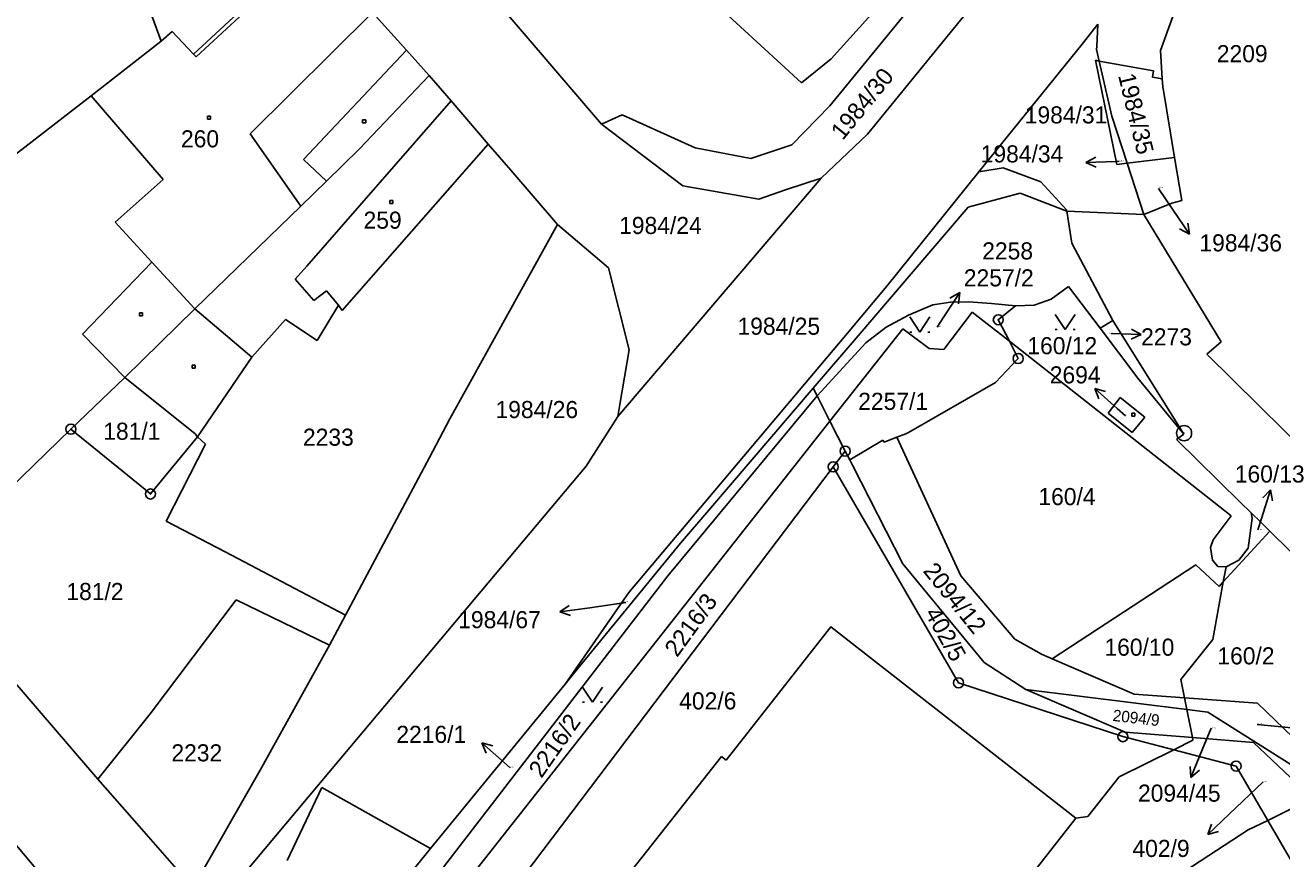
# Model space of a CAD drawing. Extents: x -795483 to -789093, y -1112258 to -1108741.
# Drawn here: x -791614.7 to -791489.6, y -1110839.7 to -1110756.8 of the extents above; entities that cross this region are included whole.
import ezdxf

# ---------------------------------------------------------------- set-up
doc = ezdxf.new("R2010")
doc.units = 0
for name, color, linetype in [('Komunikace', 7, 'Continuous'), ('Vrstva 1', 7, 'Continuous'), ('Vrstva 14', 7, 'Continuous'), ('Vrstva 15', 7, 'Continuous'), ('Vrstva 16', 7, 'Continuous'), ('Vrstva 2', 7, 'Continuous'), ('Vrstva 23', 7, 'Continuous'), ('Vrstva 25', 7, 'Continuous'), ('Vrstva 28', 7, 'Continuous')]:
    doc.layers.add(name, color=color, linetype=linetype)

msp = doc.modelspace()

# ---------------------------------------------------------------- linework, layer by layer
at = {"layer": 'Komunikace'}
for p, q in [((-791505.83, -1110770.29), (-791506.12, -1110770.3)), ((-791501.9, -1110772.99), (-791500.5, -1110775.07)), ((-791523.94, -1110786.79), (-791523.33, -1110785.87)), ((-791506.62, -1110787.43), (-791506.61, -1110787.43)), ((-791505.18, -1110795.61), (-791506.01, -1110794.88)), ((-791492, -1110806.97), (-791491.64, -1110805.83)), ((-791554.89, -1110814.18), (-791558.49, -1110814.7)), ((-791496.67, -1110826.69), (-791497.54, -1110828.83)), ((-791492.08, -1110826.31), (-791489.98, -1110826.52)), ((-791566.41, -1110830.63), (-791566.98, -1110830.13)), ((-791491.5, -1110832.03), (-791494.83, -1110835.21))]:
    msp.add_line(p, q, dxfattribs=at)
at = {"layer": 'Vrstva 1'}
for p, q in [((-791557.32, -1110766.6), (-791576.75, -1110743.88)), ((-791604.15, -1110750.16), (-791601.15, -1110758.36)), ((-791525.05, -1110749.65), (-791534.46, -1110760.12)), ((-791523.41, -1110751.11), (-791534.59, -1110764.78)), ((-791590.39, -1110752.64), (-791597.91, -1110759.63)), ((-791576.73, -1110759.25), (-791580.1, -1110755.51)), ((-791537.41, -1110762.48), (-791545.52, -1110755.06)), ((-791530.87, -1110767.6), (-791520.59, -1110755)), ((-791507.95, -1110756.65), (-791508.05, -1110758.87)), ((-791501.7, -1110759.26), (-791500.47, -1110755.89)), ((-791600.06, -1110757.38), (-791601.15, -1110758.36)), ((-791597.91, -1110759.63), (-791600.06, -1110757.38)), ((-791601.15, -1110758.36), (-791608.09, -1110763.77)), ((-791574.46, -1110761.76), (-791576.73, -1110759.25)), ((-791508.05, -1110758.87), (-791508.06, -1110759.18)), ((-791508.06, -1110759.18), (-791507.8, -1110760.32)), ((-791501.52, -1110762.1), (-791501.7, -1110759.26)), ((-791534.46, -1110760.12), (-791537.41, -1110762.48)), ((-791508.16, -1110760.25), (-791506.03, -1110770.61)), ((-791507.8, -1110760.32), (-791508.16, -1110760.25)), ((-791507.8, -1110760.32), (-791506.56, -1110765.8)), ((-791507.8, -1110760.32), (-791502.39, -1110761.31)), ((-791574.46, -1110761.76), (-791581.41, -1110769.04)), ((-791572.29, -1110764.29), (-791574.46, -1110761.76)), ((-791502.39, -1110761.31), (-791502.5, -1110761.93)), ((-791502.5, -1110761.93), (-791501.52, -1110762.1)), ((-791501.52, -1110762.1), (-791501.47, -1110762.86)), ((-791501.47, -1110762.86), (-791500.3, -1110769.93)), ((-791608.09, -1110763.77), (-791635.81, -1110785.17)), ((-791600.94, -1110772.11), (-791608.09, -1110763.77)), ((-791568.6, -1110768.59), (-791572.29, -1110764.29)), ((-791555.27, -1110765.66), (-791557.32, -1110766.6)), ((-791548.02, -1110768.95), (-791555.27, -1110765.66)), ((-791534.59, -1110764.78), (-791538.38, -1110768.66)), ((-791557.32, -1110766.6), (-791549.24, -1110772.73)), ((-791506.56, -1110765.8), (-791505.03, -1110770.49)), ((-791535.47, -1110771.97), (-791530.87, -1110767.6)), ((-791581.41, -1110769.04), (-791584.7, -1110772.26)), ((-791568.6, -1110768.59), (-791583.14, -1110785.13)), ((-791566.36, -1110771.19), (-791568.6, -1110768.59)), ((-791542.47, -1110770.01), (-791548.02, -1110768.95)), ((-791538.38, -1110768.66), (-791542.47, -1110770.01)), ((-791506.03, -1110770.61), (-791505.03, -1110770.49)), ((-791505.03, -1110770.49), (-791500.3, -1110769.93)), ((-791503.37, -1110775.6), (-791505.03, -1110770.49)), ((-791499.58, -1110774.19), (-791500.3, -1110769.93)), ((-791561.7, -1110776.6), (-791566.36, -1110771.19)), ((-791555.71, -1110795.69), (-791535.47, -1110771.97)), ((-791539, -1110773.15), (-791535.47, -1110771.97)), ((-791528.94, -1110782.71), (-791519.78, -1110771.36)), ((-791519.78, -1110771.36), (-791517.34, -1110770.93)), ((-791517.34, -1110770.93), (-791513.61, -1110772.34)), ((-791605.73, -1110776.36), (-791600.94, -1110772.11)), ((-791584.7, -1110772.26), (-791587.25, -1110774.75)), ((-791549.24, -1110772.73), (-791541.68, -1110774.05)), ((-791541.68, -1110774.05), (-791539, -1110773.15)), ((-791513.61, -1110772.34), (-791511.04, -1110775.12)), ((-791520.85, -1110774.86), (-791515.65, -1110773.46)), ((-791515.65, -1110773.46), (-791511.01, -1110775.27)), ((-791503.37, -1110775.6), (-791500.58, -1110774.47)), ((-791500.58, -1110774.47), (-791499.58, -1110774.19)), ((-791587.25, -1110774.75), (-791597.78, -1110784.98)), ((-791532, -1110787.88), (-791520.85, -1110774.86)), ((-791511.04, -1110775.12), (-791511.01, -1110775.27)), ((-791511.01, -1110775.27), (-791503.37, -1110775.6)), ((-791510.54, -1110778.44), (-791511.01, -1110775.27)), ((-791503.37, -1110775.6), (-791495.65, -1110788.26)), ((-791602.06, -1110780.34), (-791605.73, -1110776.36)), ((-791569.03, -1110789.83), (-791561.7, -1110776.6)), ((-791561.7, -1110776.6), (-791556.63, -1110780.89)), ((-791510.54, -1110778.44), (-791506.46, -1110786.14)), ((-791608.98, -1110787.48), (-791602.06, -1110780.34)), ((-791556.63, -1110780.89), (-791554.58, -1110789.04)), ((-791512.57, -1110784), (-791510.84, -1110782.74)), ((-791510.84, -1110782.74), (-791507.71, -1110786.9)), ((-791524.34, -1110784.59), (-791522.61, -1110784.3)), ((-791522.61, -1110784.3), (-791520.8, -1110784.26)), ((-791520.8, -1110784.26), (-791518.52, -1110784.44)), ((-791518.52, -1110784.44), (-791516.12, -1110784.69)), ((-791514.26, -1110784.6), (-791512.57, -1110784)), ((-791597.78, -1110784.98), (-791604.77, -1110791.79)), ((-791583.49, -1110784.62), (-791585.62, -1110788.13)), ((-791583.14, -1110785.13), (-791583.49, -1110784.62)), ((-791528.99, -1110786.8), (-791526.76, -1110785.59)), ((-791526.76, -1110785.59), (-791524.34, -1110784.59)), ((-791523.27, -1110789.02), (-791520.43, -1110785.3)), ((-791520.43, -1110785.3), (-791516.74, -1110788.2)), ((-791517.84, -1110786.06), (-791516.12, -1110784.69)), ((-791516.12, -1110784.69), (-791514.26, -1110784.6)), ((-791588.76, -1110786.04), (-791592.11, -1110789.77)), ((-791585.62, -1110788.13), (-791588.76, -1110786.04)), ((-791534.59, -1110796.15), (-791527.34, -1110786.97)), ((-791531.01, -1110788.36), (-791528.99, -1110786.8)), ((-791527.34, -1110786.97), (-791524.71, -1110788.93)), ((-791517.46, -1110786.8), (-791517.84, -1110786.06)), ((-791517.46, -1110786.8), (-791516.74, -1110788.2)), ((-791507.71, -1110786.9), (-791506.46, -1110786.14)), ((-791507.71, -1110786.9), (-791503.97, -1110791.88)), ((-791506.46, -1110786.14), (-791499.38, -1110797.43)), ((-791604.77, -1110791.79), (-791608.98, -1110787.48)), ((-791536.27, -1110792.87), (-791532, -1110787.88)), ((-791516.74, -1110788.2), (-791494.66, -1110805.56)), ((-791516.74, -1110788.2), (-791515.86, -1110789.91)), ((-791495.65, -1110788.26), (-791497.1, -1110789.47)), ((-791554.58, -1110789.04), (-791555.51, -1110794.5)), ((-791535.88, -1110793.62), (-791531.01, -1110788.36)), ((-791524.71, -1110788.93), (-791523.27, -1110789.02)), ((-791497.1, -1110789.47), (-791478.33, -1110808.03)), ((-791592.11, -1110789.77), (-791597.51, -1110797.69)), ((-791572.41, -1110795.93), (-791569.03, -1110789.83)), ((-791515.86, -1110789.91), (-791518.11, -1110792.3)), ((-791604.77, -1110791.79), (-791610.12, -1110796.94)), ((-791597.77, -1110797.41), (-791604.77, -1110791.79)), ((-791503.97, -1110791.88), (-791499.38, -1110797.43)), ((-791536.27, -1110792.87), (-791546.66, -1110805)), ((-791536.27, -1110792.87), (-791535.88, -1110793.62)), ((-791518.11, -1110792.3), (-791526.78, -1110797.26)), ((-791555.51, -1110794.5), (-791555.71, -1110795.69)), ((-791550.73, -1110811.52), (-791535.88, -1110793.62)), ((-791535.88, -1110793.62), (-791534.59, -1110796.15)), ((-791506.91, -1110795.34), (-791505.7, -1110793.79)), ((-791505.7, -1110793.79), (-791503.27, -1110795.76)), ((-791558.84, -1110800.63), (-791555.71, -1110795.69)), ((-791504.52, -1110797.29), (-791506.91, -1110795.34)), ((-791503.27, -1110795.76), (-791504.52, -1110797.29)), ((-791610.12, -1110796.94), (-791624.88, -1110811.16)), ((-791610.12, -1110796.94), (-791602.21, -1110803.39)), ((-791578.3, -1110851.53), (-791534.59, -1110796.15)), ((-791574.45, -1110799.76), (-791572.41, -1110795.93)), ((-791534.59, -1110796.15), (-791533.08, -1110799.12)), ((-791602.21, -1110803.39), (-791597.51, -1110797.69)), ((-791597.51, -1110797.69), (-791597.77, -1110797.41)), ((-791596.72, -1110798.42), (-791597.51, -1110797.69)), ((-791529.33, -1110798.03), (-791532.63, -1110800)), ((-791529.2, -1110798.23), (-791529.33, -1110798.03)), ((-791527.95, -1110797.73), (-791529.2, -1110798.23)), ((-791527.04, -1110797.41), (-791527.95, -1110797.73)), ((-791527.95, -1110797.73), (-791521.58, -1110811.54)), ((-791526.78, -1110797.26), (-791527.04, -1110797.41)), ((-791499.38, -1110797.43), (-791500.12, -1110797.97)), ((-791500.12, -1110797.97), (-791493.77, -1110804.2)), ((-791600.65, -1110806.08), (-791596.72, -1110798.42)), ((-791534.26, -1110800.69), (-791533.08, -1110799.12)), ((-791533.08, -1110799.12), (-791532.63, -1110800)), ((-791584.45, -1110831.1), (-791558.84, -1110800.63)), ((-791582.79, -1110815.43), (-791574.45, -1110799.76)), ((-791574.8, -1110854.23), (-791534.26, -1110800.69)), ((-791534.26, -1110800.69), (-791521.79, -1110822.18)), ((-791532.63, -1110800), (-791532.35, -1110800.53)), ((-791532.35, -1110800.53), (-791527.33, -1110810.34)), ((-791605.22, -1110850.5), (-791647.25, -1110801.07)), ((-791492.67, -1110805.28), (-791493.77, -1110804.2)), ((-791546.66, -1110805), (-791549.47, -1110808.29)), ((-791494.66, -1110805.56), (-791496.47, -1110807.95)), ((-791492.99, -1110808.79), (-791492.58, -1110805.78)), ((-791492.58, -1110805.78), (-791492.67, -1110805.28)), ((-791491.73, -1110806.2), (-791492.67, -1110805.28)), ((-791594.78, -1110809.15), (-791600.65, -1110806.08)), ((-791491.73, -1110806.2), (-791490.83, -1110807.08)), ((-791496.47, -1110807.95), (-791496.72, -1110808.7)), ((-791490.83, -1110807.08), (-791495.46, -1110812.14)), ((-791486.83, -1110811), (-791490.83, -1110807.08)), ((-791582.79, -1110815.43), (-791594.78, -1110809.15)), ((-791560.28, -1110821.49), (-791549.47, -1110808.29)), ((-791496.72, -1110808.7), (-791496.52, -1110809.97)), ((-791493.9, -1110809.99), (-791492.99, -1110808.79)), ((-791519.25, -1110820.14), (-791527.33, -1110810.34)), ((-791498.2, -1110810.44), (-791512.48, -1110819.79)), ((-791498.2, -1110810.44), (-791495.88, -1110812.6)), ((-791496.52, -1110809.97), (-791495.98, -1110810.59)), ((-791495.98, -1110810.59), (-791495.18, -1110810.64)), ((-791495.18, -1110810.64), (-791495.46, -1110812.14)), ((-791495.18, -1110810.64), (-791493.9, -1110809.99)), ((-791580.34, -1110849.96), (-791550.73, -1110811.52)), ((-791521.58, -1110811.54), (-791516.18, -1110817.82)), ((-791560.95, -1110822.31), (-791554.62, -1110813.19)), ((-791495.46, -1110812.14), (-791496.51, -1110817.85)), ((-791495.46, -1110812.14), (-791495.88, -1110812.6)), ((-791593.67, -1110813.93), (-791602.25, -1110825.26)), ((-791584.39, -1110818.43), (-791593.67, -1110813.93)), ((-791584.39, -1110818.43), (-791582.79, -1110815.43)), ((-791516.18, -1110817.82), (-791513.53, -1110819.34)), ((-791496.51, -1110817.85), (-791499.68, -1110821.85)), ((-791607.45, -1110831.76), (-791618.71, -1110818.65)), ((-791591.29, -1110830.86), (-791584.39, -1110818.43)), ((-791513.53, -1110819.34), (-791512.48, -1110819.79)), ((-791510.13, -1110835.65), (-791530.55, -1110819.68)), ((-791515.09, -1110822.85), (-791519.25, -1110820.14)), ((-791512.48, -1110819.79), (-791504.32, -1110823.3)), ((-791560.95, -1110822.31), (-791560.28, -1110821.49)), ((-791499.68, -1110821.85), (-791499.32, -1110823.66)), ((-791574.34, -1110838.66), (-791560.95, -1110822.31)), ((-791521.79, -1110822.18), (-791505.44, -1110827.53)), ((-791515.09, -1110822.85), (-791505.22, -1110827.08)), ((-791499.08, -1110824.84), (-791515.09, -1110822.85)), ((-791504.32, -1110823.3), (-791499.32, -1110823.66)), ((-791499.32, -1110823.66), (-791499.08, -1110824.84)), ((-791499.32, -1110823.66), (-791498.4, -1110823.73)), ((-791498.4, -1110823.73), (-791492.04, -1110824.2)), ((-791492.04, -1110824.2), (-791483.14, -1110832.78)), ((-791602.25, -1110825.26), (-791607.45, -1110831.76)), ((-791499.08, -1110824.84), (-791498.52, -1110827.63)), ((-791496.99, -1110825.1), (-791499.08, -1110824.84)), ((-791488.09, -1110830.7), (-791496.99, -1110825.1)), ((-791505.44, -1110827.53), (-791500.39, -1110828.84)), ((-791498.52, -1110827.63), (-791505.22, -1110827.08)), ((-791498.47, -1110827.89), (-791500.39, -1110828.84)), ((-791498.52, -1110827.63), (-791498.47, -1110827.89)), ((-791492.46, -1110828.12), (-791498.52, -1110827.63)), ((-791492.46, -1110828.12), (-791486.94, -1110833.33)), ((-791558.89, -1110846.63), (-791545.39, -1110829.5)), ((-791545.39, -1110829.5), (-791544.92, -1110829.88)), ((-791500.39, -1110828.84), (-791505.82, -1110831.54)), ((-791500.39, -1110828.84), (-791494.18, -1110830.46)), ((-791491.03, -1110835.86), (-791494.18, -1110830.46)), ((-791603.32, -1110836.45), (-791607.45, -1110831.76)), ((-791601.94, -1110851.92), (-791584.45, -1110831.1)), ((-791597.97, -1110842.53), (-791591.29, -1110830.86)), ((-791505.82, -1110831.54), (-791508.92, -1110835.48)), ((-791585.15, -1110832.59), (-791588.59, -1110839.85)), ((-791585.15, -1110832.59), (-791574.34, -1110838.66)), ((-791487.29, -1110834.03), (-791491.03, -1110835.86)), ((-791508.92, -1110835.48), (-791510.13, -1110835.65)), ((-791597.97, -1110842.53), (-791603.32, -1110836.45)), ((-791492.97, -1110836.81), (-791499.29, -1110840.92)), ((-791491.03, -1110835.86), (-791492.97, -1110836.81)), ((-791486.66, -1110843.36), (-791491.03, -1110835.86)), ((-791574.34, -1110838.66), (-791582.34, -1110848.43))]:
    msp.add_line(p, q, dxfattribs=at)
for points in [[(-791519.78, -1110771.36), (-791509.5, -1110758.63), (-791507.95, -1110756.65)], [(-791554.62, -1110813.19), (-791532.84, -1110787.38), (-791528.94, -1110782.71)], [(-791530.55, -1110819.68), (-791534.49, -1110816.59), (-791544.92, -1110829.88)], [(-791523.23, -1110862.08), (-791520.01, -1110857.95), (-791524.72, -1110854.28), (-791510.13, -1110835.65)]]:
    msp.add_lwpolyline(points, dxfattribs=at)
at = {"layer": 'Vrstva 16'}
for p, q in [((-791509.12, -1110770.41), (-791508.14, -1110769.87)), ((-791506.12, -1110770.3), (-791509.12, -1110770.41)), ((-791509.12, -1110770.41), (-791508.1, -1110770.87)), ((-791500.5, -1110775.07), (-791498.83, -1110777.56)), ((-791498.83, -1110777.56), (-791499.8, -1110777.01)), ((-791498.83, -1110777.56), (-791498.97, -1110776.45)), ((-791523.33, -1110785.87), (-791521.68, -1110783.36)), ((-791521.68, -1110783.36), (-791522.65, -1110783.92)), ((-791521.68, -1110783.36), (-791521.81, -1110784.47)), ((-791503.61, -1110787.52), (-791504.59, -1110786.99)), ((-791506.61, -1110787.43), (-791503.61, -1110787.52)), ((-791503.61, -1110787.52), (-791504.63, -1110787.99)), ((-791506.01, -1110794.88), (-791508.25, -1110792.89)), ((-791508.25, -1110792.89), (-791507.84, -1110793.93)), ((-791508.25, -1110792.89), (-791507.17, -1110793.18)), ((-791491.64, -1110805.83), (-791490.74, -1110802.97)), ((-791490.74, -1110802.97), (-791491.52, -1110803.77)), ((-791490.74, -1110802.97), (-791490.57, -1110804.07)), ((-791561.46, -1110815.13), (-791560.54, -1110814.49)), ((-791558.49, -1110814.7), (-791561.46, -1110815.13)), ((-791561.46, -1110815.13), (-791560.4, -1110815.48)), ((-791489.98, -1110826.52), (-791486.99, -1110826.81)), ((-791566.98, -1110830.13), (-791569.23, -1110828.15)), ((-791569.23, -1110828.15), (-791568.81, -1110829.18)), ((-791569.23, -1110828.15), (-791568.15, -1110828.43)), ((-791497.54, -1110828.83), (-791498.67, -1110831.61)), ((-791498.67, -1110831.61), (-791498.76, -1110830.49)), ((-791498.67, -1110831.61), (-791497.83, -1110830.87)), ((-791494.83, -1110835.21), (-791497, -1110837.28)), ((-791497, -1110837.28), (-791496.62, -1110836.23)), ((-791497, -1110837.28), (-791495.93, -1110836.95))]:
    msp.add_line(p, q, dxfattribs=at)
at = {"layer": 'Vrstva 2'}
for p, q in [((-791585.95, -1110749.02), (-791597.64, -1110759.92)), ((-791592.28, -1110767.57), (-791580.1, -1110755.51)), ((-791586.97, -1110770.13), (-791576.73, -1110759.25)), ((-791597.91, -1110759.63), (-791597.64, -1110759.92)), ((-791572.29, -1110764.29), (-791586.66, -1110780.72)), ((-791587.25, -1110774.75), (-791592.28, -1110767.57)), ((-791584.7, -1110772.26), (-791586.97, -1110770.13)), ((-791602.06, -1110780.34), (-791597.78, -1110784.98)), ((-791586.66, -1110780.72), (-791587.79, -1110782.02)), ((-791587.79, -1110782.02), (-791585.94, -1110784.16)), ((-791585.94, -1110784.16), (-791584.7, -1110783.17)), ((-791584.7, -1110783.17), (-791583.49, -1110784.62)), ((-791597.78, -1110784.98), (-791592.11, -1110789.77))]:
    msp.add_line(p, q, dxfattribs=at)
at = {"layer": 'Vrstva 23'}
for p, q in [((-791512.18, -1110785.52), (-791511.18, -1110787.02)), ((-791511.18, -1110787.02), (-791510.18, -1110785.52)), ((-791526.65, -1110785.78), (-791525.65, -1110787.28)), ((-791525.65, -1110787.28), (-791524.65, -1110785.78)), ((-791512.18, -1110787.02), (-791511.98, -1110787.02)), ((-791510.38, -1110787.02), (-791510.18, -1110787.02)), ((-791526.65, -1110787.28), (-791526.45, -1110787.28)), ((-791524.85, -1110787.28), (-791524.65, -1110787.28)), ((-791559.21, -1110822.6), (-791558.21, -1110824.1)), ((-791558.21, -1110824.1), (-791557.21, -1110822.6)), ((-791559.21, -1110824.1), (-791559.01, -1110824.1)), ((-791557.41, -1110824.1), (-791557.21, -1110824.1))]:
    msp.add_line(p, q, dxfattribs=at)
at = {"layer": 'Vrstva 25'}
for p, q in [((-791596.53, -1110765.8), (-791596.23, -1110765.8)), ((-791596.53, -1110766.1), (-791596.53, -1110765.8)), ((-791596.23, -1110766.1), (-791596.53, -1110766.1)), ((-791596.23, -1110765.8), (-791596.23, -1110766.1)), ((-791581.09, -1110766.18), (-791580.79, -1110766.18)), ((-791581.09, -1110766.48), (-791581.09, -1110766.18)), ((-791580.79, -1110766.48), (-791581.09, -1110766.48)), ((-791580.79, -1110766.18), (-791580.79, -1110766.48)), ((-791578.4, -1110774.19), (-791578.1, -1110774.19)), ((-791578.4, -1110774.49), (-791578.4, -1110774.19)), ((-791578.1, -1110774.49), (-791578.4, -1110774.49)), ((-791578.1, -1110774.19), (-791578.1, -1110774.49)), ((-791603.29, -1110785.38), (-791602.99, -1110785.38)), ((-791603.29, -1110785.68), (-791603.29, -1110785.38)), ((-791602.99, -1110785.68), (-791603.29, -1110785.68)), ((-791602.99, -1110785.38), (-791602.99, -1110785.68)), ((-791598.04, -1110790.56), (-791597.74, -1110790.56)), ((-791598.04, -1110790.86), (-791598.04, -1110790.56)), ((-791597.74, -1110790.56), (-791597.74, -1110790.86)), ((-791597.74, -1110790.86), (-791598.04, -1110790.86)), ((-791504.55, -1110795.34), (-791504.25, -1110795.34)), ((-791504.55, -1110795.64), (-791504.55, -1110795.34)), ((-791504.25, -1110795.64), (-791504.55, -1110795.64)), ((-791504.25, -1110795.34), (-791504.25, -1110795.64))]:
    msp.add_line(p, q, dxfattribs=at)
at = {"layer": 'Vrstva 28'}
for centre, radius in [((-791517.84, -1110786.06), 0.5), ((-791517.84, -1110786.06), 0.01), ((-791515.86, -1110789.91), 0.5), ((-791515.86, -1110789.91), 0.01), ((-791610.12, -1110796.94), 0.5), ((-791610.12, -1110796.94), 0.01), ((-791499.35, -1110797.34), 0.75), ((-791499.35, -1110797.34), 0.01), ((-791533.08, -1110799.12), 0.5), ((-791533.08, -1110799.12), 0.01), ((-791534.26, -1110800.69), 0.5), ((-791534.26, -1110800.69), 0.01), ((-791602.21, -1110803.39), 0.5), ((-791602.21, -1110803.39), 0.01), ((-791521.79, -1110822.18), 0.5), ((-791521.79, -1110822.18), 0.01), ((-791505.44, -1110827.53), 0.5), ((-791505.44, -1110827.53), 0.01), ((-791494.18, -1110830.46), 0.5), ((-791494.18, -1110830.46), 0.01)]:
    msp.add_circle(centre, radius, dxfattribs=at)

# ---------------------------------------------------------------- texts
at = {"layer": 'Vrstva 14'}
for s, height, p in [('2209', 1.7, (-791496.1, -1110760.44)), ('1984/31', 1.7, (-791515.21, -1110766.53)), ('1984/34', 0.1, (-791505.83, -1110770.29)), ('1984/36', 0.1, (-791501.9, -1110772.99)), ('1984/24', 1.7, (-791555.57, -1110777.53)), ('2258', 1.7, (-791519.44, -1110780.06)), ('1984/25', 1.7, (-791543.79, -1110787.55)), ('2257/2', 0.1, (-791523.94, -1110786.79)), ('160/12', 1.7, (-791514.95, -1110789.49)), ('2273', 0.1, (-791506.8, -1110787.43)), ('2257/1', 1.7, (-791531.78, -1110795.02)), ('1984/26', 1.7, (-791567.87, -1110795.84)), ('181/1', 1.7, (-791606.9, -1110798)), ('2233', 1.7, (-791587.03, -1110798.59)), ('160/4', 1.7, (-791513.85, -1110804.5)), ('160/13', 0.1, (-791492, -1110806.97)), ('181/2', 1.7, (-791610.57, -1110813.94)), ('1984/67', 0.1, (-791555.17, -1110814.18)), ('160/10', 1.7, (-791507.28, -1110819.48)), ('160/2', 1.7, (-791496.04, -1110820.34)), ('402/6', 1.7, (-791549.59, -1110824.82)), ('2094/45', 0.1, (-791496.67, -1110826.69)), ('2094/47', 0.1, (-791492.08, -1110826.31)), ('2232', 1.7, (-791600.12, -1110829.99)), ('2216/1', 0.1, (-791566.41, -1110830.63)), ('402/9', 0.1, (-791491.5, -1110832.03))]:
    msp.add_text(s, height=height, dxfattribs=at).set_placement(p)
for s, height, rotation, p in [('1984/30', 1.7, 50.8628, (-791533.32, -1110768.28)), ('1984/35', 1.7, 283.687, (-791505.93, -1110761.76)), ('2094/12', 1.7, 308.8223, (-791525.4, -1110811.07)), ('2216/3', 1.7, 54, (-791549.8, -1110819.71)), ('402/5', 1.7, 299.0065, (-791525.2, -1110815.25)), ('2216/2', 1.7, 54.9507, (-791563.3, -1110831.74)), ('2094/9', 1.14, 353.4783, (-791506.5, -1110825.96))]:
    msp.add_text(s, height=height, rotation=rotation, dxfattribs=at).set_placement(p)
at = {"layer": 'Vrstva 15'}
for s, height, p in [('260', 1.7, (-791599.17, -1110768.91)), ('259', 1.7, (-791581, -1110777)), ('2694', 0.1, (-791505.35, -1110795.61))]:
    msp.add_text(s, height=height, dxfattribs=at).set_placement(p)
at = {"layer": 'Vrstva 16'}
for s, p in [('1984/34', (-791519.59, -1110770.41)), ('1984/36', (-791497.83, -1110779.26)), ('2257/2', (-791521.27, -1110782.74)), ('2273', (-791503.63, -1110788.61)), ('2694', (-791512.72, -1110792.39)), ('160/13', (-791494.31, -1110802.25)), ('1984/67', (-791571.58, -1110816.74)), ('2216/1', (-791577.74, -1110828.15)), ('2094/45', (-791503.94, -1110834)), ('402/9', (-791504.49, -1110839.5))]:
    msp.add_text(s, height=1.7, dxfattribs=at).set_placement(p)

doc.saveas('drawing.dxf')
